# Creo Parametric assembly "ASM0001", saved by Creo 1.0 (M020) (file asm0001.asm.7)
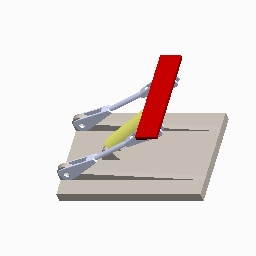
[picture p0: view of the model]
Units: millimeter Newton Second (mmNs); MM, TONNE, SECS

Other parameters: SPRING_LENGTH_UNSTRETCHED

Created from: ASSEMBLAGERELEVAGE.ASM

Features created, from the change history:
  component "BRAS.PRT" (7 times)
  datum axis "AA_1"
  datum axis "AA_2"
  datum plane "ADTM1"
  datum axis "AA_3"
  component "SUPPORT.PRT" (3 times)
  component "CORPS_VERIN.PRT"
  component "TIGE_PISTON.PRT" (2 times)
  feature "Ressort 1" (2 times)
  feature "Amortisseur 1" (2 times)
  component "SUPPORTBIS.PRT"
  component "SOCLEBIS"
  component "CORPS_VERIN"
  component "TIGE_PISTON"
  component "SUPPORTBIS"
  component "BRAS" (2 times)

Other named items: ASM_RIGHT, ASM_TOP, ASM_FRONT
